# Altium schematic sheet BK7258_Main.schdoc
size 450 x 226 mm
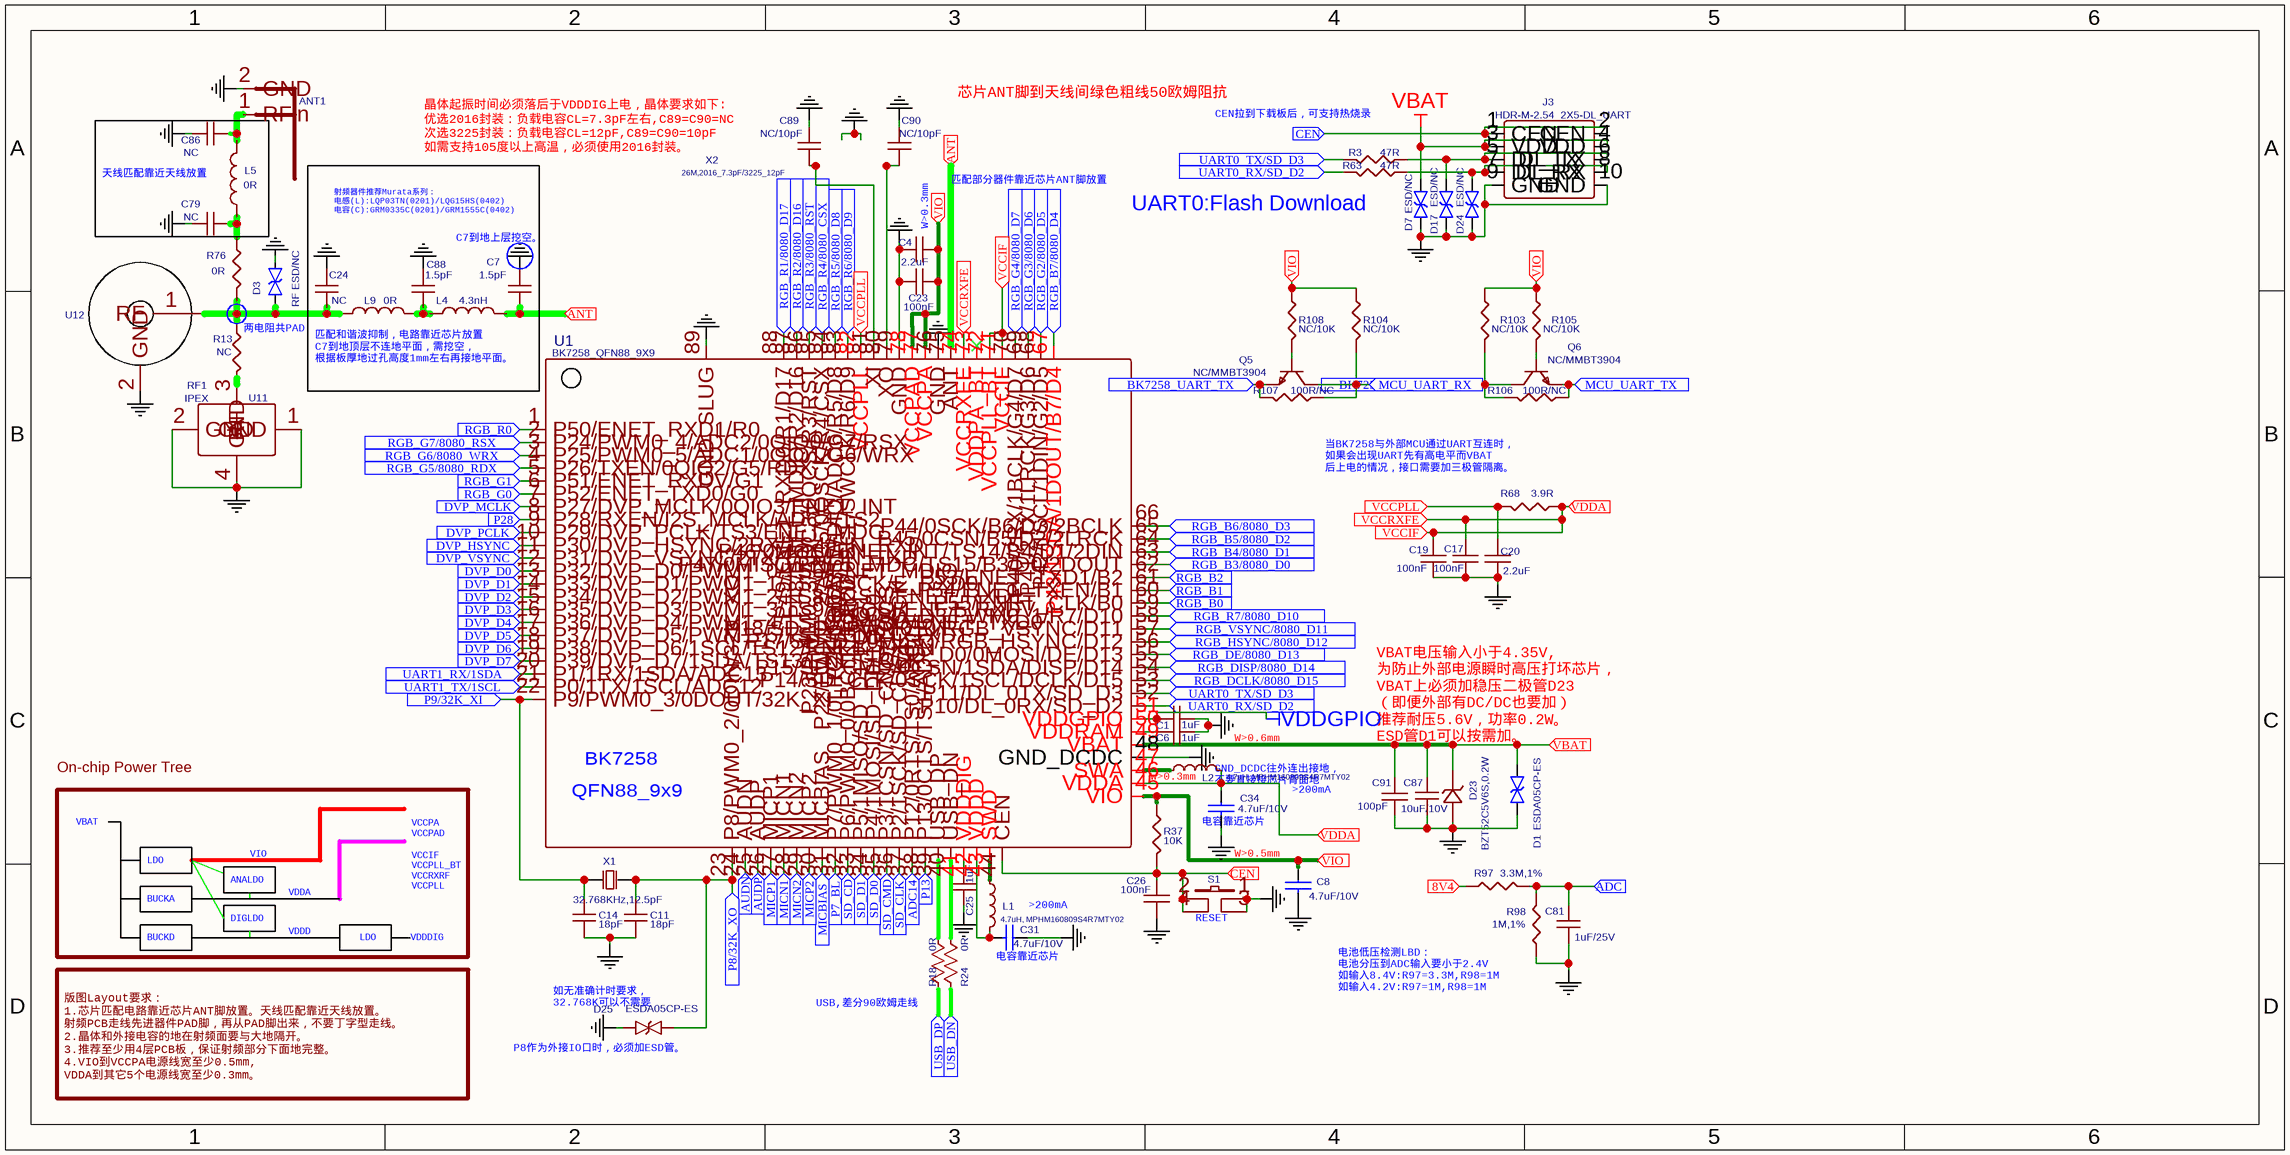
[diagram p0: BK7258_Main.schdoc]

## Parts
ANT1  ANT_PIFA  [ANT_F]  (value not drawn)
C1  1uF  [C0402]
C4  2.2uF  [C0402]
C6  1uF  [C0402]
C7  1.5pF  [C0201]
C8  4.7uF/10V  [C0603]
C11  18pF  [C0201]
C14  18pF  [C0201]
C17  100nF  [C0402]
C19  100nF  [C0402]
C20  2.2uF  [C0402]
C23  100nF  [C0402]
C24  NC  [C0201]
C25  1uF  [C0402]
C26  100nF  [C0402]
C31  4.7uF/10V  [C0603]
C34  4.7uF/10V  [C0603]
C79  NC  [C0201]
C81  1uF/25V  [C0603]
C86  NC  [C0201]
C87  10uF/10V  [C0603]
C88  1.5pF  [C0201]
C89  NC/10pF  [C0201]
C90  NC/10pF  [C0201]
C91  100pF  [C0402]
D1  ESDA05CP-ES  [DFN1006-2L-BI]
D3  RF ESD/NC  [ESD0402]
D7  ESD/NC  [ESD0402]
D17  ESD/NC  [ESD0402]
D23  BZT52C5V6S,0.2W  [SOD-323_L1.8-W1.3-LS2.5-RD]
D24  ESD/NC  [ESD0402]
D25  ESDA05CP-ES  [ESD0402]
J3  HDR-M-2.54_2X5-DL_UART  [HDR-M-2.54_2X5-DL_UART]
L1  4.7uH, MPHM160809S4R7MTY02  [L0805]
L2  4.7uH, MPHM160809S4R7MTY02  [L0805]
L4  4.3nH  [L0201]
L5  0R  [L0201]
L9  0R  [L0201]
Q5  NC/MMBT3904  [SOT-23-3_L2.9-W1.3-P1.90-LS2.4-BR]
Q6  NC/MMBT3904  [SOT-23-3_L2.9-W1.3-P1.90-LS2.4-BR]
R3  47R  [R0402]
R13  NC  [R0201]
R18  0R  [R0402]
R24  0R  [R0402]
R37  10K  [R0402]
R63  47R  [R0402]
R68  3.9R  [R0402]
R76  0R  [R0201]
R97  3.3M,1%  [R0402]
R98  1M,1%  [R0402]
R103  NC/10K  [R0402]
R104  NC/10K  [R0402]
R105  NC/10K  [R0402]
R106  100R/NC  [R0402]
R107  100R/NC  [R0402]
R108  NC/10K  [R0402]
S1  KEY  [4PIN_SWITCH_SMD_4.5MM]  (value not drawn)
U1  BK7258_QFN88_9X9  [QFN88_9X9_BK7258]
U11  IPEX  [20579-001E]  (value not drawn)
U12  RF_Test  [RF_TP]  (value not drawn)
X1  32.768KHz,12.5pF  [OSC-SMD_L2.0-W1.2]
X2  26M,2016_7.3pF/3225_12pF  [3225_2016]

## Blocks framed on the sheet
天线匹配靠近天线放置: C79 C86 L5
C7到地上层挖空。: C7 C24 C88 L4 L9

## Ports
8V4 (in), ADC14 (in), ADC (in), ANT (in), AUDN (in), AUDP (in), BK7258_UART_RX (in), BK7258_UART_TX (in), CEN (in), DVP_D0 (in), DVP_D1 (in), DVP_D2 (in), DVP_D3 (in), DVP_D4 (in), DVP_D5 (in), DVP_D6 (in), DVP_D7 (in), DVP_HSYNC (in), DVP_MCLK (in), DVP_PCLK (in), DVP_VSYNC (in), MCU_UART_RX (in), MCU_UART_TX (in), MICBIAS (in), MICN1 (in), MICN2 (in), MICP1 (in), MICP2 (in), P7_BL (in), P8/32K_XO (in), P9/32K_XI (in), P13 (in), P28 (in), RGB_B0 (in), RGB_B1 (in), RGB_B2 (in), RGB_B3/8080_D0 (in), RGB_B4/8080_D1 (in), RGB_B5/8080_D2 (in), RGB_B6/8080_D3 (in), RGB_B7/8080_D4 (in), RGB_DCLK/8080_D15 (in), RGB_DE/8080_D13 (in), RGB_DISP/8080_D14 (in), RGB_G0 (in), RGB_G1 (in), RGB_G2/8080_D5 (in), RGB_G3/8080_D6 (in), RGB_G4/8080_D7 (in), RGB_G5/8080_RDX (in), RGB_G6/8080_WRX (in), RGB_G7/8080_RSX (in), RGB_HSYNC/8080_D12 (in), RGB_R0 (in), RGB_R1/8080_D17 (in), RGB_R2/8080_D16 (in), RGB_R3/8080_RST (in), RGB_R4/8080_CSX (in), RGB_R5/8080_D8 (in), RGB_R6/8080_D9 (in), RGB_R7/8080_D10 (in), RGB_VSYNC/8080_D11 (in), SD_CD (in), SD_CLK (in), SD_CMD (in), SD_D0 (in), SD_D1 (in), UART0_RX/SD_D2 (in), UART0_TX/SD_D3 (in), UART1_RX/1SDA (in), UART1_TX/1SCL (in), USB_DN (in), USB_DP (in), VBAT (in), VCCIF (in), VCCPLL (in), VCCRXFE (in), VDDA (in), VIO (in)

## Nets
GGND: ANT1.2(GND) C1.1 C4.2 C6.1 C7.2 C8.2 C17.1 C19.1 C20.1 C23.2 C24.2 C25.1 C26.2 C31.1 C34.2 C79.1 C81.2 C86.1 C87.2 C88.2 C89.1 C90.1 C91.1 D1.1 D3.1 D7.2 D17.2 D23.2(A) D24.2 J3.9(GND) J3.10(GND) R98.2 S1.1 S1.3 U1.48(GND_DCDC) U1.76(GND) U1.79(GND) U1.89(GND_SLUG) U11.1(GND) U11.2(GND) U11.4(GND) U12.2(GND)
GND: C11.2 C14.2 D25.2
VBAT: D7.1 J3.3(VDD) J3.4(VDD)
VDDGPIO: C1.2 U1.51(VDDGPIO)
8V4: R97.2 ; port 8V4
ADC: C81.1 R97.1 R98.1 ; port ADC
ADC14: U1.37(P12/0RTS/TS0/ADC14) ; port ADC14
ANT: C7.1 L4.2 U1.75(ANT) ; port ANT
AUDN: U1.24(AUDN) ; port AUDN
AUDP: U1.25(AUDP) ; port AUDP
BK7258_UART_RX: Q5.3(C) Q6.3(C) R103.1 R104.1 R106.2 R107.1 ; port BK7258_UART_RX, port MCU_UART_RX
BK7258_UART_TX: Q5.2(E) R107.2 ; port BK7258_UART_TX
CEN: C26.1 J3.1(CEN) J3.2(CEN) R37.1 S1.2 S1.4 U1.44(CEN) ; port CEN
DVP_D0: U1.12(P32/DVP_D0/PWM1_0/TS6/ENET_MDIO) ; port DVP_D0
DVP_D1: U1.13(P33/DVP_D1/PWM1_1/TS7/0SCK/E_RXD0) ; port DVP_D1
DVP_D2: U1.14(P34/DVP_D2/PWM1_2/TS8/0CSN/ENET_RXD1) ; port DVP_D2
DVP_D3: U1.15(P35/DVP_D3/PWM1_3/TS9/0MOSI/ENET_RXDV) ; port DVP_D3
DVP_D4: U1.16(P36/DVP_D4/PWM1_4/TS10/0MISO/ENET_TXD0) ; port DVP_D4
DVP_D5: U1.17(P37/DVP_D5/PWM1_5/TS11/ENET_TXD1) ; port DVP_D5
DVP_D6: U1.18(P38/DVP_D6/1SCL/TS12/ENET_TXEN) ; port DVP_D6
DVP_D7: U1.19(P39/DVP_D7/1SDA/TS13/ENET_CLK) ; port DVP_D7
DVP_HSYNC: U1.10(P30/DVP_HSYNC/2RX/TS4/LIN_RXD) ; port DVP_HSYNC
DVP_MCLK: U1.7(P27/DVP_MCLK/0QIO3/ENET_INT) ; port DVP_MCLK
DVP_PCLK: U1.9(P29/DVP_PCLK/TS3/ENET_MDC) ; port DVP_PCLK
DVP_VSYNC: U1.11(P31/DVP_VSYNC/2TX/TS5/LIN_TXD) ; port DVP_VSYNC
MCU_UART_TX: Q6.2(E) R106.1 ; port MCU_UART_TX
MICBIAS: U1.30(MICBIAS) ; port MICBIAS
MICN1: U1.27(MICN1) ; port MICN1
MICN2: U1.28(MICN2) ; port MICN2
MICP1: U1.26(MICP1) ; port MICP1
MICP2: U1.29(MICP2) ; port MICP2
P7_BL: U1.31(P7/PWM0_1/0LRCK/1QIO3) ; port P7_BL
P8/32K_XO: C11.1 D25.1 U1.23(P8/PWM0_2/0DIN/32K_XO) X1.1(OSC1) ; port P8/32K_XO
P9/32K_XI: C14.1 U1.22(P9/PWM0_3/0DOUT/32K_XI) X1.2(OSC2) ; port P9/32K_XI
P13: U1.38(P13/0CTS/TS1/ADC15) ; port P13
P28: U1.8(P28/RXEN/I2S_MCLK/ADC4/TS2) ; port P28
RGB_B0: U1.60(P55/ENET_CLK/B0) ; port RGB_B0
RGB_B1: U1.61(P54/ENET_TXEN/B1) ; port RGB_B1
RGB_B2: U1.62(P53/ENET_TXD1/B2) ; port RGB_B2
RGB_B3/8080_D0: U1.63(P47/0MISO/ENET_MDC/TS15/B3/D0/2DOUT) ; port RGB_B3/8080_D0
RGB_B4/8080_D1: U1.64(P46/0MOSI/ENET_INT/TS14/B4/D1/2DIN) ; port RGB_B4/8080_D1
RGB_B5/8080_D2: U1.65(P45/0CSN/B5/D2/2LRCK) ; port RGB_B5/8080_D2
RGB_B6/8080_D3: U1.66(P44/0SCK/B6/D3/2BCLK) ; port RGB_B6/8080_D3
RGB_B7/8080_D4: U1.67(P43/1SDA/1DOUT/B7/D4) ; port RGB_B7/8080_D4
RGB_DCLK/8080_D15: U1.54(P14/SD_CLK/0SCK/1SCL/DCLK/D15) ; port RGB_DCLK/8080_D15
RGB_DE/8080_D13: U1.56(P16/SD_D0/0MOSI/DE/D13) ; port RGB_DE/8080_D13
RGB_DISP/8080_D14: U1.55(P15/SD_CMD/0CSN/1SDA/DISP/D14) ; port RGB_DISP/8080_D14
RGB_G0: U1.6(P52/ENET_TXD0/G0) ; port RGB_G0
RGB_G1: U1.5(P51/ENET_RXDV/G1) ; port RGB_G1
RGB_G2/8080_D5: U1.68(P42/1SCL/1DIN/G2/D5) ; port RGB_G2/8080_D5
RGB_G3/8080_D6: U1.69(P41/2TX/1LRCK/G3/D6) ; port RGB_G3/8080_D6
RGB_G4/8080_D7: U1.70(P40/2RX/1BCLK/G4/D7) ; port RGB_G4/8080_D7
RGB_G5/8080_RDX: U1.4(P26/TXEN/0QIO2/G5/RDX) ; port RGB_G5/8080_RDX
RGB_G6/8080_WRX: U1.3(P25/PWM0_5/ADC1/0QIO1/G6/WRX) ; port RGB_G6/8080_WRX
RGB_G7/8080_RSX: U1.2(P24/PWM0_4/ADC2/0QIO0/G7/RSX) ; port RGB_G7/8080_RSX
RGB_HSYNC/8080_D12: U1.57(P17/SD_D1/0MISO/RGB_HSYNC/D12) ; port RGB_HSYNC/8080_D12
RGB_R0: U1.1(P50/ENET_RXD1/R0) ; port RGB_R0
RGB_R1/8080_D17: U1.88(P49/ENET_RXD0/R1/D17) ; port RGB_R1/8080_D17
RGB_R2/8080_D16: U1.87(P48/ENET_MDIO/R2/D16) ; port RGB_R2/8080_D16
RGB_R3/8080_RST: U1.86(P23/PWM0_3/ADC3/0QCS/R3/RST) ; port RGB_R3/8080_RST
RGB_R4/8080_CSX: U1.85(P22/PWM0_2/ADC5/0QSCK/R4/CSX) ; port RGB_R4/8080_CSX
RGB_R5/8080_D8: U1.84(P21/0SDA/SWDIO/ADC6/R5/D8) ; port RGB_R5/8080_D8
RGB_R6/8080_D9: U1.83(P20/0SCL/SWCLK/R6/D9) ; port RGB_R6/8080_D9
RGB_R7/8080_D10: U1.59(P19/SD_D3/PWM0_1/R7/D10) ; port RGB_R7/8080_D10
RGB_VSYNC/8080_D11: U1.58(P18/SD_D2/PWM0_0/RGB_VSYNC/D11) ; port RGB_VSYNC/8080_D11
SD_CD: U1.32(P6/PWM0_0/0BCLK/1QIO2) ; port SD_CD
SD_CLK: U1.36(P2/1SCK/SD_CLK/1QSCK) ; port SD_CLK
SD_CMD: U1.35(P3/1CSN/SD_CMD/1QCS) ; port SD_CMD
SD_D0: U1.34(P4/1MOSI/SD_D0/1QIO0) ; port SD_D0
SD_D1: U1.33(P5/1MISO/SD_D1/1QIO1) ; port SD_D1
UART0_RX/SD_D2: R63.2 U1.52(P10/DL_0RX/SD_D2) ; port UART0_RX/SD_D2
UART0_TX/SD_D3: R3.2 U1.53(P11/DL_0TX/SD_D3) ; port UART0_TX/SD_D3
UART1_RX/1SDA: U1.20(P1/1RX/1SDA/ADC13) ; port UART1_RX/1SDA
UART1_TX/1SCL: U1.21(P0/1TX/1SCL/ADC12) ; port UART1_TX/1SCL
USB_DN: R24.1 ; port USB_DN
USB_DP: R18.1 ; port USB_DP
VBAT: C87.1 C91.2 D1.2 D23.1(K) U1.49(VBAT) ; port VBAT  [a separate net that carries the same name]
VCCIF: C17.2 C19.2 C34.1 L2.2 R68.1 U1.46(VDDA) U1.71(VCCIF) U1.72(VCCPLL_BT) U1.74(VCCRXFE) ; port VCCRXFE, port VCCIF, port VDDA
VCCPLL: C20.2 R68.2 U1.82(VCCPLL) ; port VCCPLL
VIO: C4.1 C8.1 C23.1 R37.2 R103.2 R104.2 R105.2 R108.2 U1.45(VIO) U1.77(VCCPA) U1.78(VCCPAD) ; port VIO
NetANT1_1: ANT1.1(RFin) C86.2 L5.2
NetC6_2: C6.2 U1.50(VDDRAM)
NetC24_1: C24.1 D3.2 L9.1 R13.2 R76.1 U12.1(RF)
NetC25_2: C25.2 U1.41(VDDDIG)
NetC31_2: C31.2 L1.2 U1.42(VDDD)
NetC79_2: C79.2 L5.1 R76.2
NetC88_1: C88.1 L4.1 L9.2
NetC89_2: C89.2 U1.81(XI)
NetC90_2: C90.2 U1.80(XO)
NetD17_1: D17.1 J3.5(DL_TX) J3.6(DL_TX) R3.1
NetD24_1: D24.1 J3.7(DL_RX) J3.8(DL_RX) R63.1
NetL1_1: L1.1 U1.43(SWD)
NetL2_1: L2.1 U1.47(SWA)
NetQ5_1: Q5.1(B) R108.1
NetQ6_1: Q6.1(B) R105.1
NetR13_1: R13.1 U11.3(RF)
NetR18_2: R18.2 U1.39(USB_DP)
NetR24_2: R24.2 U1.40(USB_DN)

Not connected (* = marked no-connect by the designer): U1 73(VDDPA_BT)*

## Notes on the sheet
- 芯片ANT脚到天线间绿色粗线50欧姆阻抗
- 晶体起振时间必须落后于VDDDIG上电，晶体要求如下:
  优选2016封装：负载电容CL=7.3pF左右,C89=C90=NC
  次选3225封装：负载电容CL=12pF,C89=C90=10pF
  如需支持105度以上高温，必须使用2016封装。
- CEN拉到下载板后，可支持热烧录
- 射频器件推荐Murata系列：
  电感(L):LQP03TN(0201)/LQG15HS(0402)
  电容(C):GRM0335C(0201)/GRM1555C(0402)
- 匹配部分器件靠近芯片ANT脚放置
- (near C4) W>0.3mm
- UART0:Flash Download
- (near R13) 两电阻共PAD
- 匹配和谐波抑制，电路靠近芯片放置
  C7到地顶层不连地平面，需挖空，
  根据板厚地过孔高度1mm左右再接地平面。
- (near C19) 当BK7258与外部MCU通过UART互连时，
  如果会出现UART先有高电平而VBAT
  后上电的情况，接口需要加三极管隔离。
- VBAT电压输入小于4.35V,
  为防止外部电源瞬时高压打坏芯片，
  VBAT上必须加稳压二极管D23
  （即便外部有DC/DC也要加）
  推荐耐压5.6V，功率0.2W。
  ESD管D1可以按需加。
- On-chip Power Tree
- (near L2) W>0.3mm
- GND_DCDC往外连出接地，
  不要直接接芯片背面地
- (near L2) W>0.6mm
- >200mA
- VBAT
- (near U1) VCCIF
  VCCPLL_BT
  VCCRXRF
  VCCPLL
- (near U1) VCCPA
  VCCPAD
- (near C34) 电容靠近芯片
- BUCKA
- LDO
- DIGLDO
- ANALDO
- VIO
- VDDA
- (near S1) RESET
- W>0.5mm
- BUCKD
- VDDD
- VDDDIG
- (near D25) 如无准确计时要求，
  32.768K可以不需要
- (near C31) 电容靠近芯片
- 电池低压检测LBD：
  电池分压到ADC输入要小于2.4V
  如输入8.4V:R97=3.3M,R98=1M
  如输入4.2V:R97=1M,R98=1M
- 版图Layout要求：
  1.芯片匹配电路靠近芯片ANT脚放置。天线匹配靠近天线放置。
  射频PCB走线先进器件PAD脚，再从PAD脚出来，不要丁字型走线。
  2.晶体和外接电容的地在射频面要与大地隔开。
  3.推荐至少用4层PCB板，保证射频部分下面地完整。
  4.VIO到VCCPA电源线宽至少0.5mm,
  VDDA到其它5个电源线宽至少0.3mm。
- (near D25) P8作为外接IO口时，必须加ESD管。
- USB,差分90欧姆走线

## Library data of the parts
ANT1 = ANT_PIFA: Package Display: No
C1 C6 C25 = 1uF: Manufacturer Part Number: 0805ZC105KAT2A; Manufacturer: AVX; APN: C071-0
C4 C20 = 2.2uF: Manufacturer Part Number: 0805ZC105KAT2A; Manufacturer: AVX; APN: C071-0
C7 C88 = 1.5pF: Manufacturer Part Number: 06035A101KAT2A; Manufacturer: AVX; APN: C029-0
C8 C31 C34 = 4.7uF/10V: Manufacturer Part Number: 0805ZC105KAT2A; Manufacturer: AVX; APN: C071-0
C11 C14 = 18pF: Manufacturer Part Number: 06035A101KAT2A; Manufacturer: AVX; APN: C029-0
C17 C19 C23 C26 = 100nF: Manufacturer Part Number: 0805ZC105KAT2A; Manufacturer: AVX; APN: C071-0
C24 C79 C86 = NC: Manufacturer Part Number: 06035A101KAT2A; Manufacturer: AVX; APN: C029-0
C81 = 1uF/25V: Manufacturer Part Number: 06035A101KAT2A; Manufacturer: AVX; APN: C029-0
C87 = 10uF/10V: Manufacturer Part Number: 06035A101KAT2A; Manufacturer: AVX; APN: C029-0
C89 C90 = NC/10pF: Manufacturer Part Number: 06035A101KAT2A; Manufacturer: AVX; APN: C029-0
C91 = 100pF: Manufacturer Part Number: 0805ZC105KAT2A; Manufacturer: AVX; APN: C071-0
D1 = ESDA05CP-ES: BOM_Manufacturer: SOT23-5_SGM2019; Contributor: D-MAN
D3 = RF ESD/NC: Contributor: D-MAN
D7 D17 D24 = ESD/NC: Contributor: D-MAN
D23 = BZT52C5V6S,0.2W: Manufacturer: GOODWORK; Manufacturer Part: BZT52C5V1S; Contributor: LCSC
D25 = ESDA05CP-ES: Contributor: D-MAN
J3 = HDR-M-2.54_2X5-DL_UART: Contributor: qunshan.xu
L1 = 4.7uH, MPHM160809S4R7MTY02: Manufacturer: Sunlord(顺络); Manufacturer Part: MPH201210S4R7MT; nameAlias: Value; Contributor: lcsc; 3DModel: L0805_L2.0-W1.6-H0.9
L2 = 4.7uH, MPHM160809S4R7MTY02: Manufacturer: Sunlord(顺络); Manufacturer Part: MPH201214S4R7MT; nameAlias: Value; Contributor: LCSC
L4 = 4.3nH: Manufacturer: COILCRAFT; Manufacturer Part Number: 1008HT-R27TJBC; APN: L914-0
L5 L9 = 0R: Manufacturer: COILCRAFT; Manufacturer Part Number: 1008HT-R27TJBC; APN: L914-0
Q5 Q6 = NC/MMBT3904: Manufacturer: CJ(江苏长电/长晶); Manufacturer Part: MMBT3904(RANGE:100-300); Contributor: 立创EDA官方封装库
R3 R63 = 47R: Manufacturer Part Number: RM73B1JT240J; Manufacturer: KOA; APN: R125-0
R13 = NC: Manufacturer Part Number: RM73B1JT240J; Manufacturer: KOA; APN: R125-0
R18 R24 = 0R: nameAlias: Value(Ω); Contributor: LCEDA_Lib
R37 = 10K: Manufacturer Part Number: RM73B1JT240J; Manufacturer: KOA; APN: R125-0
R68 = 3.9R: Manufacturer Part Number: RM73B1JT240J; Manufacturer: KOA; APN: R125-0
R76 = 0R: Manufacturer Part Number: RM73B1JT240J; Manufacturer: KOA; APN: R125-0
R97 = 3.3M,1%: Manufacturer Part Number: RM73B1JT240J; Manufacturer: KOA; APN: R125-0
R98 = 1M,1%: Manufacturer Part Number: RM73B1JT240J; Manufacturer: KOA; APN: R125-0
R103-R105 R108 = NC/10K: Manufacturer Part Number: RM73B1JT240J; Manufacturer: KOA; APN: R125-0
R106 R107 = 100R/NC: Manufacturer Part Number: RM73B1JT240J; Manufacturer: KOA; APN: R125-0
S1 = KEY: Manufacturer Part Number: EP11SD1ABE; Manufacturer: C & K; APN: S001-0
U1 = BK7258_QFN88_9X9: Contributor: qunshan.xu
U11 = IPEX: Contributor: jian.shi1
U12 = RF_Test: Contributor: jian.shi1
X1 = 32.768KHz,12.5pF: Manufacturer: EPSON(爱普生); Manufacturer Part: FC-12M32.768KHZ9PF20PPM; Contributor: LCSC; nameAlias: Frequency
X2 = 26M,2016_7.3pF/3225_12pF: Contributor: qunshan.xu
